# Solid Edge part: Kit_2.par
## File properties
Last saved by: bmolnar
Revision: 78
Sűrűség: 0,000 kg/m^3
Pontosság: 0,990
Dokumentum tartalom típus: 0
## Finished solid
Body 1: solid body, 21 faces, 37 edges, 18 vertices.
  Faces by surface: cylinder 10, plane 9, cone 1, torus 1
  Edges by curve: circle 23, line 14
Bounding box of the edges (mm; curved faces can reach further): 68.000 x 67.800 x 6.000, from (-34, -32.35, 1.35) to (34, 35.45, 7.35).
Cylindrical faces by radius (mm): R1.5 x2, R3 x4, R23.5 x1, R29.65 x1, R32.35 x1, R34 x1
Conical faces (half-angle, radius in mm at the cone's reference point): 45 deg R23 x1
Toroidal faces (ring radius, tube radius in mm): R24.3 r0.8 x1
Planar faces by outward normal: +z 2, -z 5, oblique 2
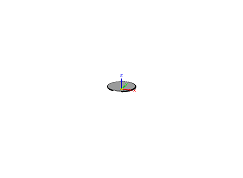
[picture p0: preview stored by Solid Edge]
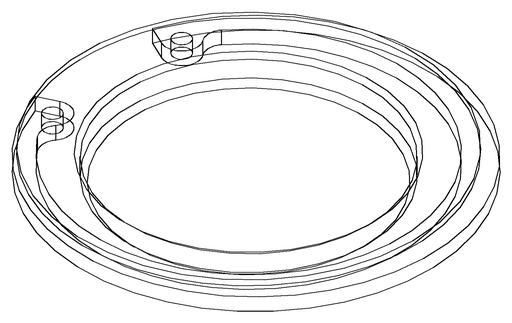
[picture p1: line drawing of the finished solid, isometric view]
